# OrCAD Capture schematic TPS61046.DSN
size B; title: TPS61046 28-V Output Voltage Boost Converter; rev: 1; note: Datasheet: SLVSCQ7  EVM Guide: SLVUAF9
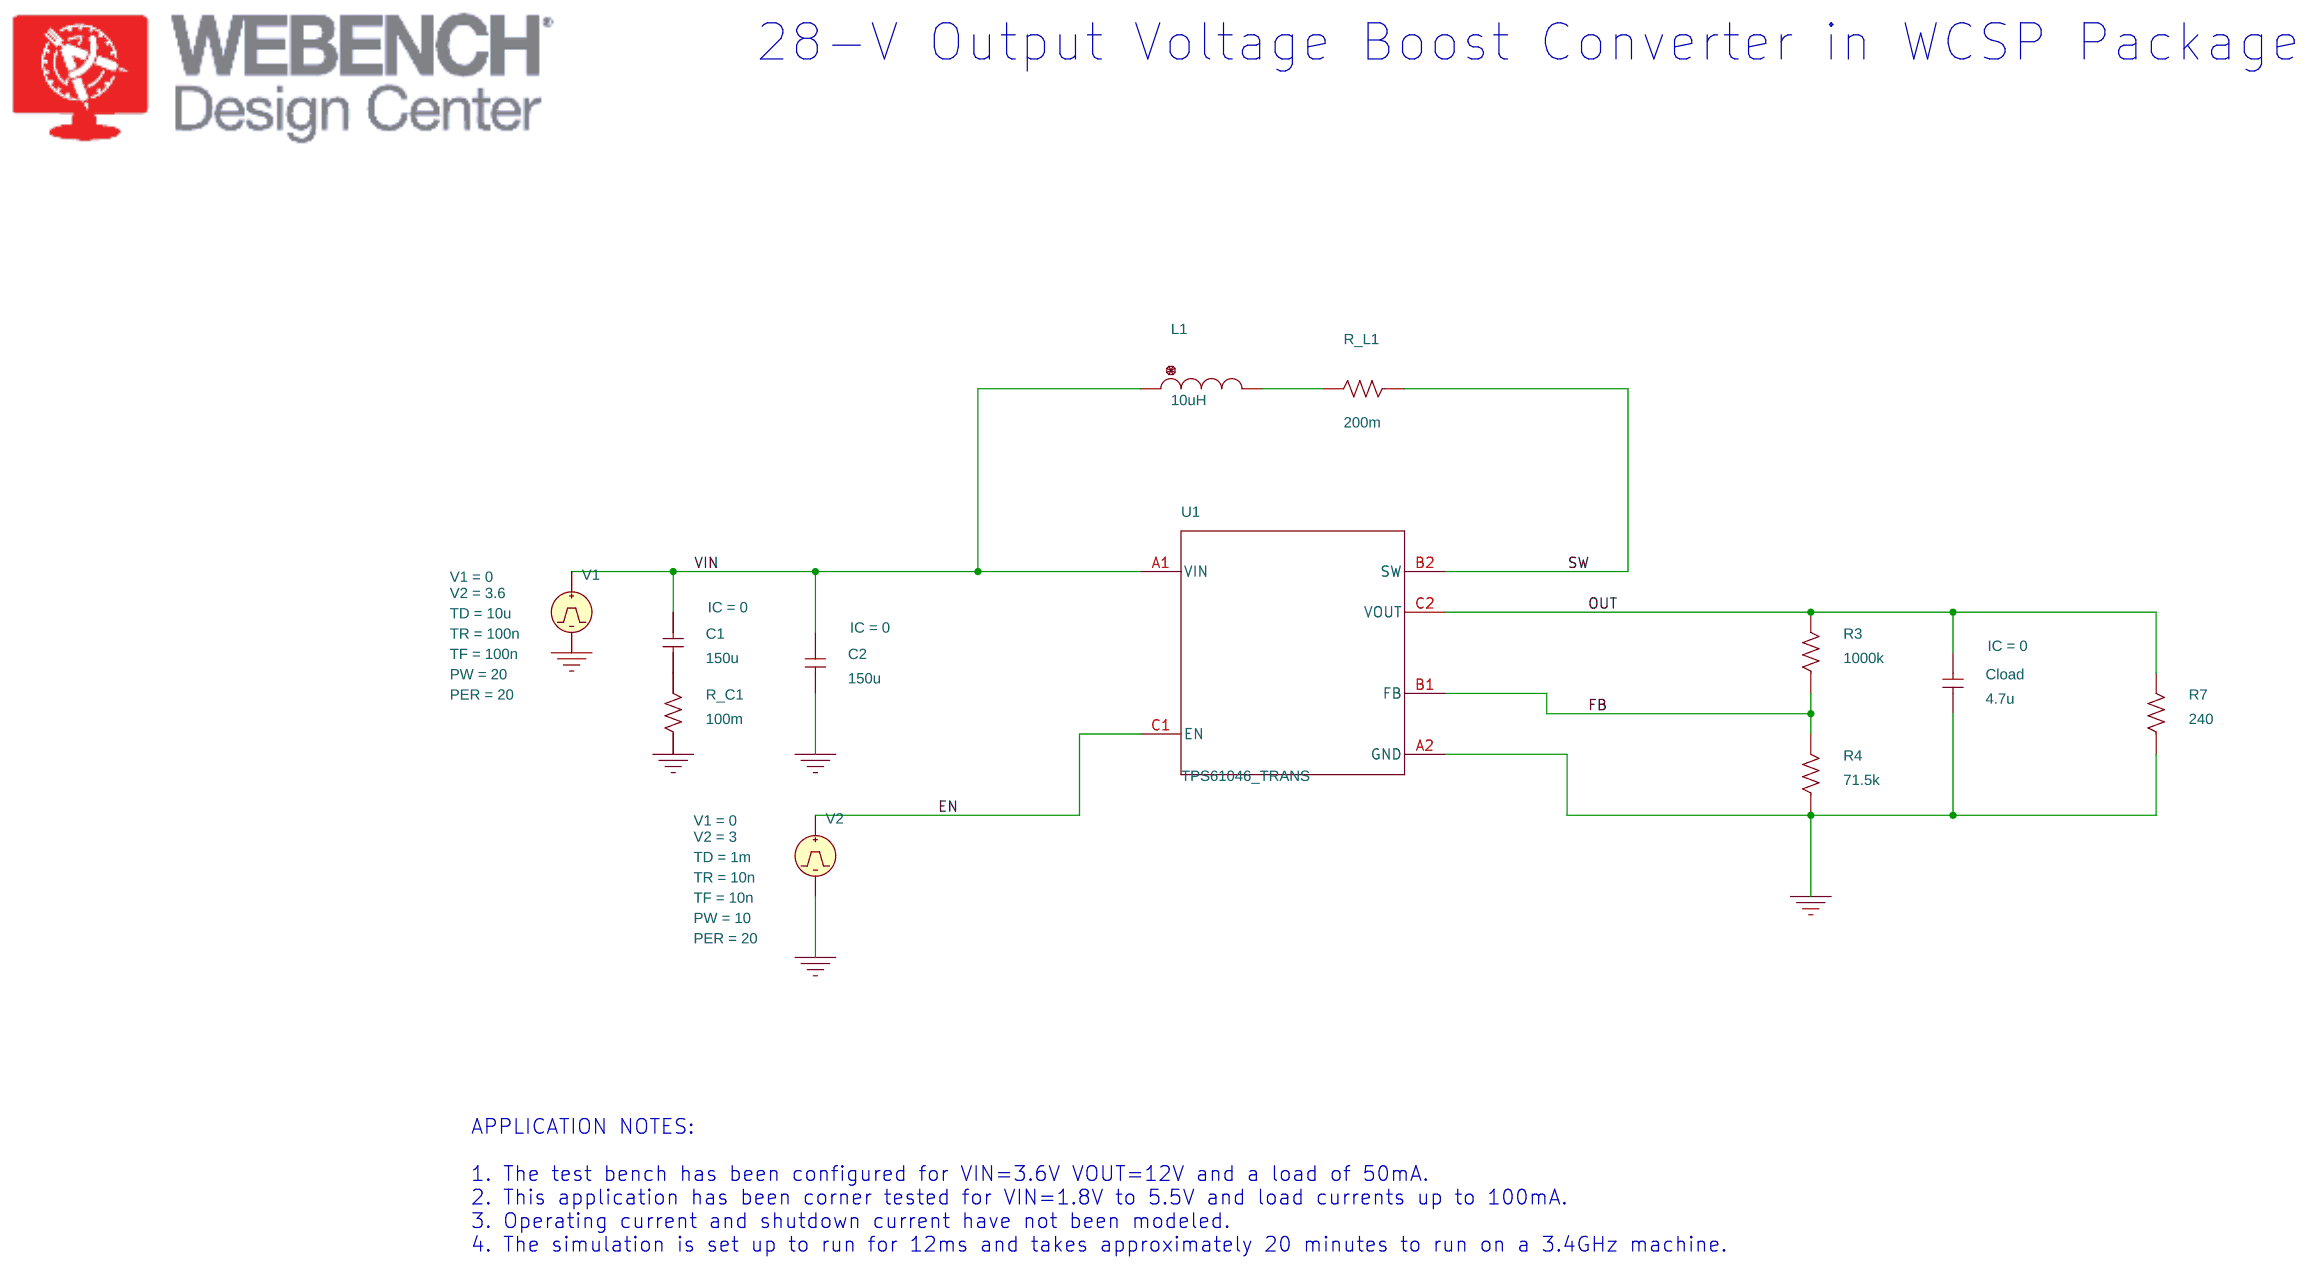
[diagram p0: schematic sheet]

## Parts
C1  150u  [RAD/CK05]
C2  150u  [RAD/CK05]
Cload  4.7u  [RAD/CK05]
L1  10uH  [DISC/.350x.175/LS.200x.100/.034]
R3  1000k  [AX/RC05]
R4  71.5k  [AX/RC05]
R7  240  [AX/RC05]
R_C1  100m  [AX/RC05]
R_L1  200m  [AX/RC05]
U1  TPS61046_TRANS  [YFF0006AAAA]
V1  VPULSE
V2  VPULSE

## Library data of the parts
C1 C2 Cload = C: IC: 0
L1 = L: IC: 0
R3 R4 R7 R_C1 R_L1 = R
U1 = TPS61046_TRANS_0
V1 = VPULSE: PER: 20; PW: 20; TD: 10u; TF: 100n; TR: 100n; V1: 0; V2: 3.6
V2 = VPULSE: PER: 20; PW: 10; TD: 1m; TF: 10n; TR: 10n; V1: 0; V2: 3

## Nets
VIN: C1.1 C2.1 L1.1 U1.A1(VIN) V1.1(+)
0: C2.2 Cload.2 R4.1 R7.1 R_C1.1 U1.A2(GND) V1.2(-) V2.2(-)
EN: U1.C1(EN) V2.1(+)
FB: R3.1 R4.2 U1.B1(FB)
OUT: Cload.1 R3.2 R7.2 U1.C2(VOUT)
SW: R_L1.1 U1.B2(SW)
N86586: L1.2 R_L1.2
N92725: C1.2 R_C1.2

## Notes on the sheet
- 28-V Output Voltage Boost Converter in WCSP Package
- APPLICATION NOTES:
  1. The test bench has been configured for VIN=3.6V VOUT=12V and a load of 50mA.
  2. This application has been corner tested for VIN=1.8V to 5.5V and load currents up to 100mA.
  3. Operating current and shutdown current have not been modeled.
  4. The simulation is set up to run for 12ms and takes approximately 20 minutes to run on a 3.4GHz machine.
